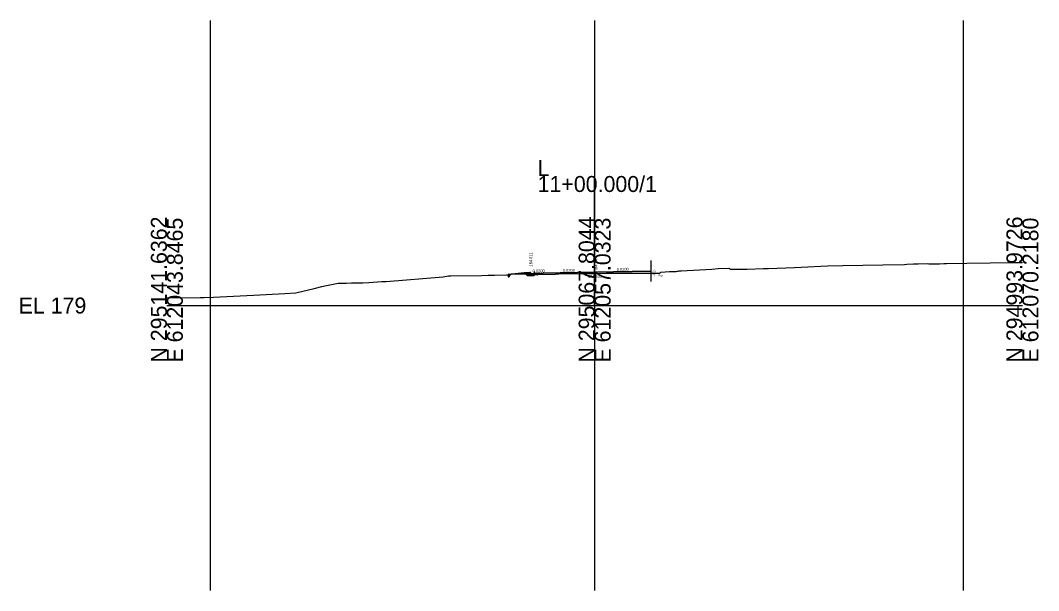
# Model space of a CAD drawing. Extents: x -81 to 616364, y 450 to 299952.
# Drawn here: x 535426.7 to 535605.2, y 117298.4 to 117398.4 of the extents above; entities that cross this region are included whole.
import ezdxf

# ---------------------------------------------------------------- set-up
doc = ezdxf.new("R2010")
doc.units = 0
for name, color, linetype in [('Exist XS Ground Line', 7, 'Continuous'), ('Old_Level_10', 7, 'Continuous'), ('Old_Level_17', 7, 'Continuous'), ('Old_Level_6', 7, 'Continuous'), ('Old_Level_63', 7, 'Continuous'), ('Prop XS Dump Level', 7, 'Continuous'), ('Prop XS Earthwork Shape', 7, 'Continuous'), ('Prop XS EOT Tick Mark', 7, 'Continuous'), ('Prop XS Exc Vertical Line 1', 7, 'Continuous'), ('Prop XS Exc Vertical Line 2', 7, 'Continuous'), ('Prop XS Exc Vertical Line 3', 7, 'Continuous'), ('Prop XS Finish Grade', 7, 'Continuous'), ('Prop XS Finish Grade Concrete', 7, 'Continuous'), ('Prop XS Finish Grade Earthwork', 7, 'Continuous'), ('Prop XS Finish Grade Pavement', 7, 'Continuous'), ('Prop XS Pvmt Edge Slope', 7, 'Continuous'), ('Prop XS Side Slope Text', 7, 'Continuous'), ('Prop XS Subgrade Concrete', 7, 'Continuous'), ('Prop XS Subgrade Earthwork', 7, 'Continuous')]:
    doc.layers.add(name, color=color, linetype=linetype)

msp = doc.modelspace()

# ---------------------------------------------------------------- linework, layer by layer
at = {"layer": 'Exist XS Ground Line'}
for points in [[(535551.14, 117354.74), (535552.97, 117354.74), (535553.32, 117354.75), (535554.09, 117354.76), (535556.94, 117354.83), (535557.84, 117354.83), (535562.42, 117355.05), (535568.16, 117355.34), (535570.85, 117355.38), (535574.4, 117355.45), (535577.86, 117355.48), (535581.71, 117355.53), (535582.08, 117355.62), (535583.28, 117355.67), (535583.76, 117355.7), (535584.08, 117355.7), (535585.68, 117355.75), (535585.94, 117355.66), (535587.85, 117355.69), (535588.6, 117355.75), (535589.03, 117355.73), (535592.61, 117355.77), (535600.8, 117355.93), (535602.36, 117355.93)], [(535452.36, 117349.72), (535458.19, 117349.74), (535458.6, 117349.74), (535458.89, 117349.74), (535460.52, 117349.83), (535467.55, 117350.19), (535473.02, 117350.47), (535474.99, 117350.57), (535478.16, 117351.36), (535479.5, 117351.72), (535480.32, 117351.85), (535482.39, 117352.27), (535483.79, 117352.3), (535484.72, 117352.35), (535486.7, 117352.35), (535487.77, 117352.38), (535490.05, 117352.56), (535490.8, 117352.57), (535500.81, 117353.4), (535501.71, 117353.54), (535502.14, 117353.55), (535507.52, 117353.64), (535508.68, 117353.66), (535509.79, 117353.68), (535511.89, 117353.74), (535512.28, 117353.73), (535512.58, 117353.77), (535512.74, 117353.87), (535514.16, 117353.89), (535515.7, 117353.91), (535516.34, 117353.93), (535516.77, 117353.91), (535516.98, 117353.78), (535520.48, 117353.87), (535521.07, 117353.89), (535524.81, 117353.96), (535525.21, 117353.96), (535525.45, 117353.96), (535527.33, 117354), (535529.42, 117354.01), (535529.59, 117354.01), (535533.19, 117354.05), (535533.34, 117354.05), (535533.9, 117354.05), (535534.16, 117354.05), (535534.29, 117354.04), (535538.29, 117354.03), (535538.63, 117354.03), (535538.77, 117354.03), (535538.95, 117354.19), (535540.49, 117354.31), (535540.91, 117354.32), (535541.23, 117354.32), (535541.45, 117354.33), (535541.64, 117354.35), (535541.84, 117354.38), (535542.02, 117354.41), (535542.2, 117354.42), (535542.37, 117354.43), (535542.53, 117354.42), (535547.9, 117354.75), (535549.03, 117354.85), (535550.89, 117354.89), (535551, 117354.85), (535551.14, 117354.74)]]:
    msp.add_lwpolyline(points, dxfattribs=at)
at = {"layer": 'Old_Level_10'}
msp.add_line((535512.37, 117353.74), (535512.37, 117353.85), dxfattribs=at)
at = {"layer": 'Old_Level_17'}
for p, q in [((535512.29, 117353.85), (535512.17, 117353.73)), ((535512.17, 117353.73), (535512.17, 117353.41)), ((535512.37, 117353.71), (535512.17, 117353.71)), ((535512.17, 117353.65), (535512.19, 117353.66)), ((535512.18, 117353.63), (535512.17, 117353.64)), ((535512.18, 117353.57), (535512.17, 117353.56)), ((535512.17, 117353.54), (535512.19, 117353.54)), ((535512.17, 117353.41), (535512.37, 117353.41)), ((535512.19, 117353.66), (535512.18, 117353.63)), ((535512.19, 117353.54), (535512.18, 117353.57)), ((535512.24, 117353.75), (535512.27, 117353.76)), ((535512.28, 117353.73), (535512.24, 117353.75)), ((535512.24, 117353.46), (535512.27, 117353.47)), ((535512.28, 117353.44), (535512.24, 117353.46)), ((535512.27, 117353.76), (535512.28, 117353.73)), ((535512.27, 117353.47), (535512.28, 117353.44)), ((535512.29, 117353.85), (535512.29, 117353.85)), ((535512.37, 117353.86), (535512.32, 117353.86)), ((535512.36, 117353.86), (535512.35, 117353.84)), ((535512.35, 117353.84), (535512.37, 117353.84)), ((535512.37, 117353.65), (535512.35, 117353.67)), ((535512.35, 117353.67), (535512.37, 117353.67)), ((535512.36, 117353.58), (535512.35, 117353.55)), ((535512.35, 117353.55), (535512.37, 117353.55)), ((535512.37, 117353.56), (535512.36, 117353.58)), ((535512.37, 117353.85), (535512.37, 117353.86)), ((535512.37, 117353.74), (535512.37, 117353.41))]:
    msp.add_line(p, q, dxfattribs=at)
for centre in [(535512.18, 117353.6), (535512.2, 117353.72), (535512.2, 117353.43), (535512.22, 117353.76), (535512.21, 117353.61), (535512.22, 117353.47), (535512.23, 117353.71), (535512.22, 117353.67), (535512.22, 117353.51), (535512.23, 117353.42), (535512.25, 117353.57), (535512.26, 117353.79), (535512.27, 117353.7), (535512.26, 117353.5), (535512.27, 117353.82), (535512.27, 117353.65), (535512.27, 117353.62), (535512.28, 117353.61), (535512.27, 117353.53), (535512.28, 117353.56), (535512.3, 117353.8), (535512.3, 117353.74), (535512.3, 117353.65), (535512.3, 117353.51), (535512.3, 117353.45), (535512.32, 117353.7), (535512.33, 117353.61), (535512.32, 117353.58), (535512.35, 117353.76), (535512.35, 117353.47), (535512.35, 117353.8), (535512.35, 117353.51), (535512.36, 117353.62)]:
    msp.add_circle(centre, 0.00196, dxfattribs=at)
for centre, radius, start, end in [((535512.18, 117353.5), 0.00196, 256.8767, 103.1233), ((535512.27, 117353.41), 0.00196, 24.915, 155.085), ((535512.32, 117353.81), 0.05, 90, 135), ((535512.32, 117353.41), 0.00196, 342.3416, 197.6584), ((535512.37, 117353.85), 0.006, 359.8812, 90), ((535512.38, 117353.8), 0.00196, 145.5013, 214.4987), ((535512.37, 117353.6), 0.00196, 17.8106, 342.1894)]:
    msp.add_arc(centre, radius, start, end, dxfattribs=at)
at = {"layer": 'Old_Level_6'}
msp.add_line((535537.26, 117352.56), (535537.26, 117356.26), dxfattribs=at)
at = {"layer": 'Old_Level_63'}
for p, q in [((535527.36, 117348.36), (535527.36, 117371.07)), ((535452.36, 117348.36), (535527.36, 117348.36)), ((535527.36, 117348.36), (535602.36, 117348.36))]:
    msp.add_line(p, q, dxfattribs=at)
at = {"layer": 'Prop XS Dump Level'}
for p, q in [((535518.36, 117354.03), (535527.36, 117354.21)), ((535527.36, 117354.21), (535537.26, 117354.41)), ((535516.76, 117354), (535518.36, 117354.03))]:
    msp.add_line(p, q, dxfattribs=at)
at = {"layer": 'Prop XS Earthwork Shape'}
for points in [[(535512.37, 117353.85), (535514.99, 117354.15), (535515.23, 117353.91), (535514.16, 117353.89), (535512.74, 117353.87), (535512.58, 117353.77), (535512.37, 117353.74)], [(535512.37, 117353.85), (535514.99, 117354.15), (535515.23, 117353.91), (535514.16, 117353.89), (535512.74, 117353.87), (535512.58, 117353.77), (535512.37, 117353.74)], [(535512.37, 117353.85), (535514.99, 117354.15), (535515.23, 117353.91), (535514.16, 117353.89), (535512.74, 117353.87), (535512.58, 117353.77), (535512.37, 117353.74)], [(535512.37, 117353.85), (535514.99, 117354.15), (535515.23, 117353.91), (535514.16, 117353.89), (535512.74, 117353.87), (535512.58, 117353.77), (535512.37, 117353.74)], [(535512.37, 117353.85), (535514.99, 117354.15), (535515.23, 117353.91), (535514.16, 117353.89), (535512.74, 117353.87), (535512.58, 117353.77), (535512.37, 117353.74)], [(535512.37, 117353.85), (535514.99, 117354.15), (535515.23, 117353.91), (535514.16, 117353.89), (535512.74, 117353.87), (535512.58, 117353.77), (535512.37, 117353.74)], [(535512.37, 117353.85), (535514.99, 117354.15), (535515.23, 117353.91), (535514.16, 117353.89), (535512.74, 117353.87), (535512.58, 117353.77), (535512.37, 117353.74)], [(535516.76, 117353.62), (535516.78, 117353.62), (535516.78, 117353.9), (535516.77, 117353.91), (535516.34, 117353.93), (535515.7, 117353.91), (535515.23, 117353.91), (535515.51, 117353.62)], [(535516.76, 117353.62), (535516.78, 117353.62), (535516.78, 117353.9), (535516.77, 117353.91), (535516.34, 117353.93), (535515.7, 117353.91), (535515.23, 117353.91), (535515.51, 117353.62)], [(535516.76, 117353.62), (535516.78, 117353.62), (535516.78, 117353.9), (535516.77, 117353.91), (535516.34, 117353.93), (535515.7, 117353.91), (535515.23, 117353.91), (535515.51, 117353.62)], [(535516.78, 117353.9), (535516.76, 117353.62), (535515.51, 117353.62), (535515.23, 117353.91), (535515.7, 117353.91), (535516.34, 117353.93)], [(535516.76, 117353.62), (535516.78, 117353.62), (535516.78, 117353.9), (535516.77, 117353.91), (535516.34, 117353.93), (535515.7, 117353.91), (535515.23, 117353.91), (535515.51, 117353.62)], [(535516.76, 117353.62), (535516.78, 117353.62), (535516.78, 117353.9), (535516.77, 117353.91), (535516.34, 117353.93), (535515.7, 117353.91), (535515.23, 117353.91), (535515.51, 117353.62)], [(535515.51, 117353.62), (535516.76, 117353.62), (535516.78, 117353.62), (535516.78, 117353.9), (535516.77, 117353.91), (535516.34, 117353.93), (535515.7, 117353.91), (535515.23, 117353.91)]]:
    msp.add_lwpolyline(points, close=True, dxfattribs=at)
at = {"layer": 'Prop XS EOT Tick Mark'}
msp.add_line((535516.76, 117354.3), (535516.76, 117354), dxfattribs=at)
at = {"layer": 'Prop XS Exc Vertical Line 1'}
msp.add_line((535459.94, 117398.36), (535459.94, 117298.36), dxfattribs=at)
at = {"layer": 'Prop XS Exc Vertical Line 2'}
msp.add_line((535527.36, 117398.36), (535527.36, 117298.36), dxfattribs=at)
at = {"layer": 'Prop XS Exc Vertical Line 3'}
msp.add_line((535591.96, 117398.36), (535591.96, 117298.36), dxfattribs=at)
at = {"layer": 'Prop XS Finish Grade'}
msp.add_line((535514.99, 117354.15), (535516.01, 117354.13), dxfattribs=at)
at = {"layer": 'Prop XS Finish Grade Concrete'}
for p, q in [((535516.09, 117354.13), (535516.01, 117354.13)), ((535516.13, 117354.12), (535516.09, 117354.13)), ((535516.13, 117354.12), (535516.15, 117354.09)), ((535516.15, 117354.09), (535516.18, 117354.01)), ((535516.18, 117354.01), (535516.2, 117353.99)), ((535516.2, 117353.99), (535516.24, 117353.98)), ((535516.24, 117353.98), (535516.76, 117354))]:
    msp.add_line(p, q, dxfattribs=at)
at = {"layer": 'Prop XS Finish Grade Earthwork'}
for q in [(535514.99, 117354.15), (535512.37, 117353.74)]:
    msp.add_line((535512.37, 117353.85), q, dxfattribs=at)
at = {"layer": 'Prop XS Finish Grade Pavement'}
for p, q in [((535527.36, 117354.21), (535518.36, 117354.03)), ((535537.26, 117354.41), (535527.36, 117354.21)), ((535518.36, 117354.03), (535516.76, 117354))]:
    msp.add_line(p, q, dxfattribs=at)
at = {"layer": 'Prop XS Pvmt Edge Slope'}
for p, q in [((535515.51, 117353.62), (535515.71, 117353.82)), ((535515.71, 117353.82), (535516.01, 117353.82))]:
    msp.add_line(p, q, dxfattribs=at)
at = {"layer": 'Prop XS Subgrade Concrete'}
for p, q in [((535516.01, 117354.13), (535516.01, 117353.82)), ((535516.01, 117353.82), (535516.76, 117353.82)), ((535516.76, 117353.82), (535516.76, 117354))]:
    msp.add_line(p, q, dxfattribs=at)
at = {"layer": 'Prop XS Subgrade Earthwork'}
for p, q in [((535514.99, 117354.15), (535515.51, 117353.62)), ((535515.51, 117353.62), (535516.76, 117353.62)), ((535516.76, 117353.62), (535516.78, 117353.62)), ((535516.78, 117353.9), (535516.78, 117353.62))]:
    msp.add_line(p, q, dxfattribs=at)

# ---------------------------------------------------------------- texts
at = {"layer": 'Old_Level_63'}
for s, p in [('L', (535517.36, 117371.07)), ('11+00.000/1', (535517.36, 117368.27)), ('EL 179', (535426.37, 117346.96))]:
    msp.add_text(s, height=2.8, dxfattribs=at).set_placement(p)
for s, p in [('N 295141.6362', (535452.36, 117338.36)), ('E 612043.8465', (535455.16, 117338.36)), ('N 295067.8044', (535527.36, 117338.36)), ('E 612057.0323', (535530.16, 117338.36)), ('N 294993.9726', (535602.36, 117338.36)), ('E 612070.2180', (535605.16, 117338.37))]:
    msp.add_text(s, height=2.8, rotation=90, dxfattribs=at).set_placement(p)
at = {"layer": 'Prop XS Dump Level'}
for p in [(535516.78, 117353.61), (535538.58, 117353.46)]:
    msp.add_text('Eop', height=0.3, dxfattribs=at).set_placement(p)
at = {"layer": 'Prop XS Side Slope Text'}
for s, rotation, p in [('184.611', 90, (535516.41, 117355.2)), (' 184.847', 90, (535527.86, 117354.21)), ('0.0200', 1.1458, (535516.49, 117354.15)), ('0.0200', 1.1458, (535521.79, 117354.25)), ('0.0200', 1.1458, (535531.24, 117354.44)), ('-Y2-', 90, (535538.01, 117353.43))]:
    msp.add_text(s, height=0.5, rotation=rotation, dxfattribs=at).set_placement(p)
msp.add_text('184.633', height=0.5, dxfattribs=at).set_placement((535526.17, 117353.23))

doc.saveas('drawing.dxf')
